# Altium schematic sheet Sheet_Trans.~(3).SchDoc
size A4
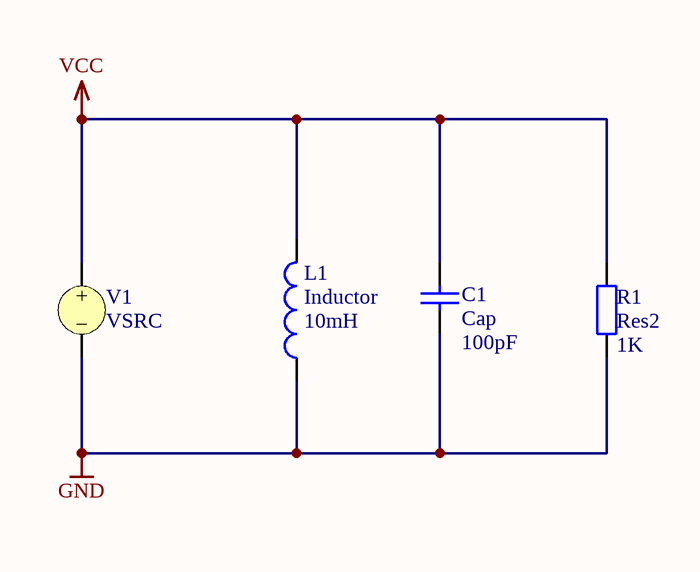
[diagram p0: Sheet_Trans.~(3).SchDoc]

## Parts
C1  Cap  value 100pF  [RAD-0.3]
L1  Inductor  value 10mH  [0402-A]
R1  Res2  value 1K  [AXIAL-0.4]
V1  VSRC

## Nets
GND: C1.1 L1.1 R1.1 V1.2
VCC: C1.2 L1.2 R1.2 V1.1

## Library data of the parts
C1 = Cap: Capacitor
L1 = Inductor: Code_IEC: 1005
R1 = Res2: Resistor
V1 = VSRC: Voltage Source; Note: PCB Footprint - Not required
